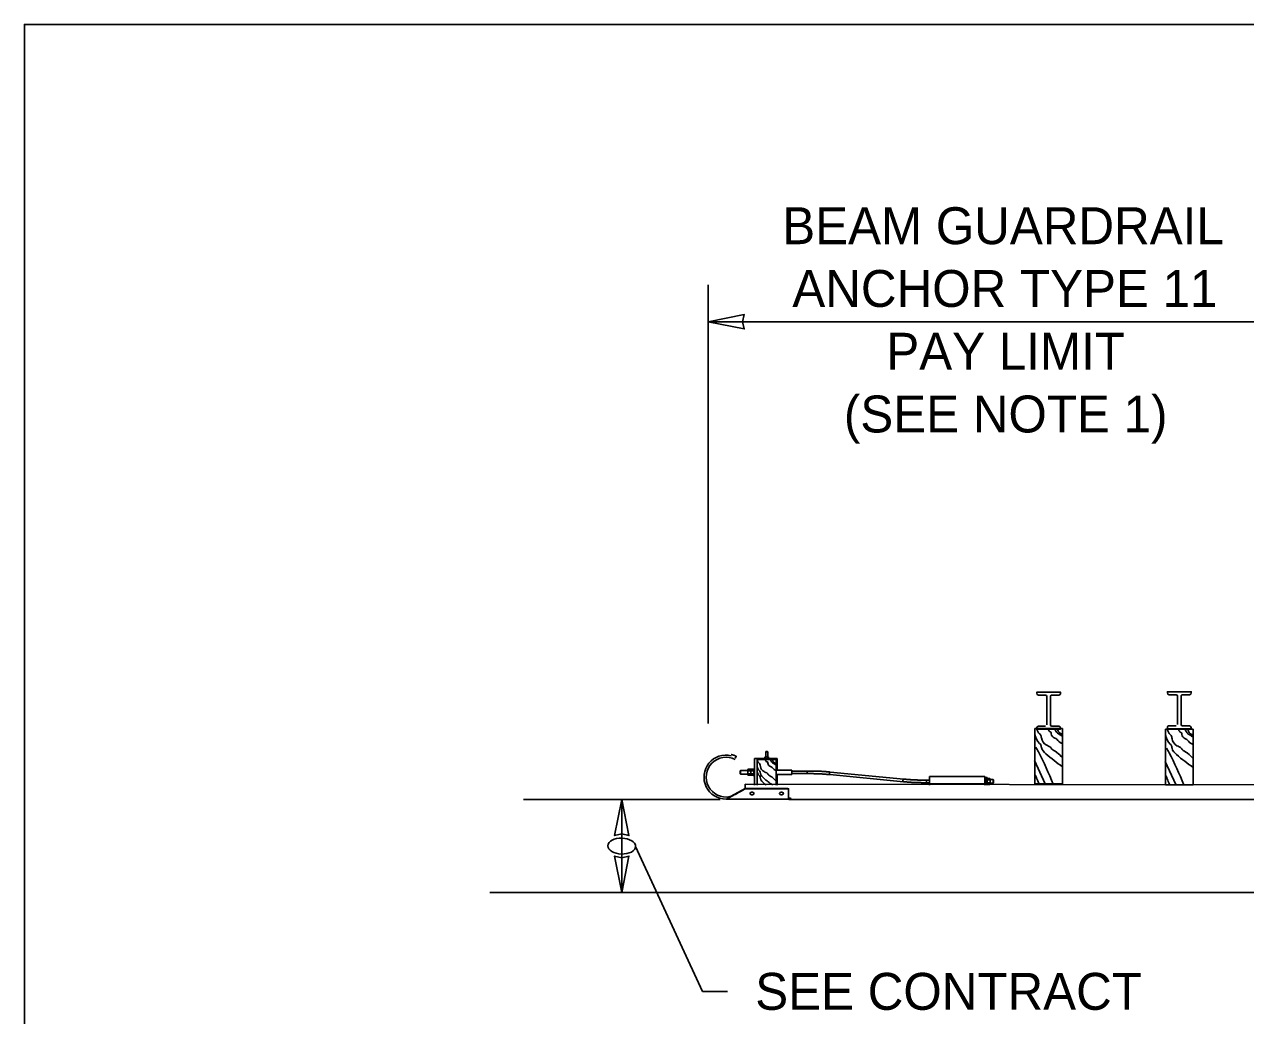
# Model space of a CAD drawing. Extents: x 99862 to 103680, y 99470 to 102076.
# Drawn here: x 99862 to 100391, y 101646 to 102076 of the extents above; entities that cross this region are included whole.
import ezdxf

# ---------------------------------------------------------------- set-up
doc = ezdxf.new("R2010")
doc.units = 0
for name, color, linetype in [('Level 1', 7, 'Continuous'), ('Level 11', 7, 'Continuous'), ('Level 13', 7, 'Continuous'), ('Level 15', 7, 'Continuous'), ('Level 18', 7, 'Continuous'), ('Level 2', 7, 'Continuous'), ('Level 20', 7, 'Continuous'), ('Level 3', 7, 'Continuous'), ('Level 4', 7, 'Continuous'), ('Level 5', 7, 'Continuous'), ('Level 6', 7, 'Continuous'), ('Level 7', 7, 'Continuous'), ('Level 9', 7, 'Continuous')]:
    doc.layers.add(name, color=color, linetype=linetype)

msp = doc.modelspace()

# ---------------------------------------------------------------- linework, layer by layer
at = {"layer": 'Level 1'}
msp.add_lwpolyline([(99862, 99999.5), (103151, 99999.5), (103151, 102075.5), (99862, 102075.5)], close=True, dxfattribs=at)
at = {"layer": 'Level 11'}
msp.add_line((100063.75, 101699.31), (101794.56, 101699.31), dxfattribs=at)
at = {"layer": 'Level 13'}
for p, q in [((100299.86, 101756.4), (100304.44, 101746.38)), ((100356.48, 101756.08), (100361.06, 101746.06))]:
    msp.add_line(p, q, dxfattribs=at)
for points in [[(100299.95, 101768.04), (100302.04, 101763.89), (100302.49, 101763.48), (100302.85, 101762.09), (100304.79, 101759.37), (100311.98, 101753.77)], [(100300.77, 101770.29), (100302.04, 101768.02), (100302.49, 101767.61), (100302.85, 101766.22), (100304.96, 101763.19), (100306.87, 101762.1), (100307.28, 101761.56), (100309.41, 101760.1), (100309.59, 101759.96), (100312.01, 101757.67)], [(100305.74, 101770.29), (100306.56, 101768.93), (100306.95, 101768.76), (100307.12, 101768.05), (100308.36, 101766.28), (100309.6, 101765.62), (100309.92, 101765.18), (100311.98, 101763.77)], [(100308.44, 101770.3), (100308.85, 101769.61), (100309.75, 101768.32), (100310.74, 101767.72), (100311.91, 101766.98)], [(100309.85, 101770.26), (100310.2, 101768.94), (100311.91, 101767.81)], [(100356.57, 101767.73), (100358.66, 101763.58), (100359.11, 101763.17), (100359.46, 101761.78), (100361.4, 101759.06), (100368.6, 101753.46)], [(100357.39, 101769.98), (100358.66, 101767.7), (100359.11, 101767.29), (100359.46, 101765.9), (100361.58, 101762.88), (100363.49, 101761.78), (100363.9, 101761.24), (100366.03, 101759.78), (100366.21, 101759.65), (100368.62, 101757.36)], [(100362.36, 101769.97), (100363.17, 101768.61), (100363.57, 101768.45), (100363.74, 101767.73), (100364.98, 101765.96), (100366.21, 101765.3), (100366.54, 101764.86), (100368.6, 101763.45)], [(100365.06, 101769.98), (100365.47, 101769.29), (100366.37, 101768), (100367.36, 101767.41), (100368.53, 101766.67)], [(100366.47, 101769.95), (100366.82, 101768.63), (100368.53, 101767.5)], [(100300.4, 101762.18), (100301.54, 101760.17), (100307.93, 101746.23)], [(100357.02, 101761.86), (100358.16, 101759.85), (100364.55, 101745.92)], [(100179.71, 101756.66), (100180.43, 101755.25), (100180.77, 101754.95), (100181.04, 101753.9), (100182.63, 101751.64), (100184.07, 101750.82), (100184.37, 101750.41), (100185.97, 101749.32), (100186.11, 101749.22), (100187.92, 101747.51)], [(100183.21, 101756.96), (100183.82, 101755.94), (100184.12, 101755.82), (100184.24, 101755.28), (100185.18, 101753.96), (100186.1, 101753.46), (100186.35, 101753.13), (100187.89, 101752.08)], [(100185.23, 101756.97), (100185.54, 101756.45), (100186.22, 101755.49), (100186.96, 101755.04), (100187.84, 101754.49)], [(100186.29, 101756.95), (100186.55, 101755.96), (100187.84, 101755.11)], [(100179.7, 101753.68), (100180.44, 101752.16), (100180.78, 101751.85), (100181.05, 101750.81), (100182.51, 101748.77), (100186.25, 101745.84)], [(100179.7, 101751.51), (100180.44, 101749.99), (100180.78, 101749.68), (100181.05, 101748.64), (100182.51, 101746.6), (100183.53, 101745.8)], [(100299.96, 101750.47), (100300.11, 101750.21), (100300.25, 101749.95), (100300.52, 101749.41), (100301.01, 101748.29), (100301.46, 101747.16), (100301.69, 101746.6), (100301.93, 101746.04)], [(100356.57, 101750.15), (100356.73, 101749.9), (100356.87, 101749.63), (100357.14, 101749.09), (100357.63, 101747.98), (100358.08, 101746.85), (100358.31, 101746.28), (100358.55, 101745.73)]]:
    msp.add_spline(points, degree=3, dxfattribs=at)
at = {"layer": 'Level 15'}
for p, q in [((100158.32, 101962.65), (100158.32, 101772.53)), ((100419.5, 101946.65), (100158.32, 101946.65)), ((100163.53, 101739.62), (100078.32, 101739.62)), ((100120.92, 101699.31), (100120.92, 101739.62)), ((100126.92, 101719.21), (100155.93, 101656.41)), ((100155.93, 101656.41), (100166.79, 101656.41))]:
    msp.add_line(p, q, dxfattribs=at)
for points in [[(100158.32, 101946.65), (100174.04, 101943.56), (100173.32, 101946.65), (100174.04, 101949.73)], [(100120.92, 101739.62), (100117.84, 101723.9), (100120.92, 101724.63), (100124.01, 101723.9)], [(100120.92, 101699.31), (100117.84, 101715.03), (100120.92, 101714.3), (100124.01, 101715.03)]]:
    msp.add_lwpolyline(points, close=True, dxfattribs=at)
msp.add_ellipse((100120.92, 101719.37), major_axis=(-6, 0.16), ratio=0.57735, dxfattribs=at)
at = {"layer": 'Level 18'}
for p, q in [((100556.25, 101745.69), (100174.41, 101746.25)), ((100419.5, 101739.62), (100193.38, 101739.62))]:
    msp.add_line(p, q, dxfattribs=at)
at = {"layer": 'Level 2'}
for p, q in [((100174.41, 101744.26), (100174.41, 101746.25)), ((100174.41, 101745.81), (100174.41, 101745.84))]:
    msp.add_line(p, q, dxfattribs=at)
at = {"layer": 'Level 3'}
for p, q in [((100170.56, 101758.24), (100170.13, 101757.41)), ((100183.32, 101760.21), (100183.45, 101760.34)), ((100183.32, 101760.21), (100184.26, 101760.21)), ((100183.32, 101758.03), (100183.32, 101760.21)), ((100183.45, 101760.34), (100184.12, 101760.34)), ((100184.12, 101760.34), (100184.26, 101760.21)), ((100184.26, 101760.21), (100184.26, 101758.03)), ((100174.39, 101744.26), (100166.72, 101740.19)), ((100192.77, 101744.26), (100174.39, 101744.26)), ((100192.77, 101744.15), (100174.44, 101744.14)), ((100177.56, 101742.74), (100177.23, 101742.74)), ((100177.56, 101741.64), (100177.23, 101741.64)), ((100190.31, 101742.74), (100189.98, 101742.74)), ((100190.31, 101741.64), (100189.98, 101741.64)), ((100193.14, 101744.35), (100193.14, 101744.46)), ((100193.14, 101740.42), (100193.14, 101743.85)), ((100193.14, 101740.42), (100193.14, 101739.7)), ((100193.14, 101739.7), (100174.39, 101739.7))]:
    msp.add_line(p, q, dxfattribs=at)
for radius, start, end in [(9.56, 76.3846, 270.2805), (8.62, 62.498, 281.2468)]:
    msp.add_arc((100166.14, 101749.26), radius, start, end, dxfattribs=at)
for centre, major_axis, start_param, end_param in [((100177.23, 101742.19), (0.68, 0), 1.570796, 4.712389), ((100177.56, 101742.19), (0.68, 0), 4.712389, 7.853982), ((100189.98, 101742.19), (0.68, 0), 1.570796, 4.712389), ((100190.31, 101742.19), (0.68, 0), 4.712389, 7.853982), ((100192.77, 101743.96), (-0.375, 0), 3.141593, 4.712389), ((100192.77, 101743.85), (-0.375, 0), 3.141593, 4.712389)]:
    msp.add_ellipse(centre, major_axis=major_axis, ratio=0.807578, start_param=start_param, end_param=end_param, dxfattribs=at)
for points, degree in [([(100168.39, 101759.06), (100169.62, 101758.76), (100170.56, 101758.24), (100170.56, 101758.24)], 2), ([(100174.44, 101744.14), (100171.71, 101742.66), (100168.98, 101741.18), (100166.23, 101739.72), (100166.22, 101739.71), (100166.2, 101739.71), (100166.19, 101739.7)], 3), ([(100193.52, 101739.99), (100193.49, 101739.97), (100193.43, 101739.94), (100193.34, 101739.91), (100193.25, 101739.89), (100193.18, 101739.89), (100193.14, 101739.89)], 3), ([(100193.97, 101740.24), (100193.68, 101740.08), (100193.52, 101739.99)], 2), ([(100194.34, 101740.24), (100194.19, 101740.16), (100194.06, 101740.08), (100193.77, 101739.92), (100193.61, 101739.82)], 3), ([(100174.39, 101739.7), (100171.64, 101739.7), (100168.89, 101739.7), (100166.14, 101739.7)], 2), ([(100166.19, 101739.7), (100166.19, 101739.7), (100166.19, 101739.7), (100166.19, 101739.7)], 2), ([(100193.61, 101739.82), (100193.46, 101739.74), (100193.34, 101739.7), (100193.14, 101739.7)], 2), ([(100193.14, 101739.7), (100193.14, 101739.7), (100193.14, 101739.7), (100193.14, 101739.7)], 2)]:
    msp.add_open_spline(points, degree=degree, dxfattribs=at)
at = {"layer": 'Level 4'}
for p, q in [((100299.97, 101770.29), (100311.97, 101770.29)), ((100299.97, 101770.29), (100299.97, 101746.29)), ((100311.97, 101746.29), (100311.97, 101770.29)), ((100356.59, 101769.98), (100368.59, 101769.98)), ((100356.59, 101769.98), (100356.59, 101745.98)), ((100368.59, 101745.98), (100368.59, 101769.98)), ((100182.98, 101757.34), (100179.66, 101757.34)), ((100181.54, 101757.06), (100179.66, 101757.06)), ((100187.91, 101756.96), (100179.66, 101756.96)), ((100179.66, 101756.96), (100179.66, 101745.84)), ((100188.29, 101757.34), (100184.6, 101757.34)), ((100188.01, 101757.06), (100186.04, 101757.06)), ((100187.91, 101745.84), (100187.91, 101756.96)), ((100188.01, 101752.28), (100188.01, 101757.06)), ((100188.29, 101752.28), (100188.29, 101757.34)), ((100188.01, 101745.84), (100188.01, 101750.4)), ((100188.29, 101745.84), (100188.29, 101750.4)), ((100299.97, 101746.29), (100311.97, 101746.29)), ((100356.59, 101745.98), (100368.59, 101745.98))]:
    msp.add_line(p, q, dxfattribs=at)
at = {"layer": 'Level 5'}
for p, q in [((100186.04, 101757.21), (100181.54, 101757.21)), ((100181.54, 101757.21), (100181.54, 101756.96)), ((100186.04, 101757.21), (100186.04, 101756.96))]:
    msp.add_line(p, q, dxfattribs=at)
at = {"layer": 'Level 6'}
for p, q in [((100172.29, 101751.96), (100172.42, 101752.09)), ((100172.29, 101750.72), (100172.29, 101751.96)), ((100172.29, 101751.96), (100172.29, 101751.96)), ((100172.42, 101750.59), (100172.29, 101750.72)), ((100172.42, 101750.59), (100172.42, 101752.09)), ((100172.42, 101752.09), (100175.57, 101752.09)), ((100175.57, 101750.59), (100172.42, 101750.59)), ((100187.91, 101752.28), (100194.69, 101752.28)), ((100194.69, 101750.4), (100194.69, 101752.28)), ((100194.69, 101752.28), (100194.69, 101752.28)), ((100194.69, 101751.9), (100201.24, 101751.9)), ((100201.24, 101750.78), (100194.69, 101750.78)), ((100201.24, 101751.9), (100201.24, 101750.78)), ((100211.28, 101751.46), (100243.15, 101748.41)), ((100194.69, 101750.4), (100187.91, 101750.4)), ((100243.04, 101747.29), (100211.17, 101750.34)), ((100253.08, 101747.98), (100253.08, 101746.85)), ((100253.08, 101747.98), (100254.29, 101747.98)), ((100254.29, 101746.85), (100253.08, 101746.85)), ((100254.29, 101749.55), (100278.29, 101749.55)), ((100254.29, 101749.55), (100254.29, 101746.32)), ((100254.29, 101746.32), (100278.29, 101746.32)), ((100254.29, 101746.32), (100254.29, 101745.84)), ((100278.29, 101749.55), (100278.29, 101745.84)), ((100278.29, 101749.1), (100279.04, 101749.1)), ((100279.04, 101749.1), (100279.04, 101745.84)), ((100280.6, 101748.17), (100281.9, 101748.17)), ((100281.9, 101746.67), (100280.6, 101746.67)), ((100281.9, 101748.17), (100281.9, 101746.67)), ((100281.9, 101748.17), (100282.04, 101748.03)), ((100282.04, 101746.8), (100281.9, 101746.67)), ((100282.04, 101748.03), (100282.04, 101746.8)), ((100282.04, 101746.8), (100282.04, 101746.8))]:
    msp.add_line(p, q, dxfattribs=at)
for centre, start_param in [((100211.23, 101750.9), 3.141597), ((100243.1, 101747.85), 3.141588)]:
    msp.add_ellipse(centre, major_axis=(-0.054, -0.56), ratio=0.548823, start_param=start_param, end_param=6.283185, dxfattribs=at)
for points in [[(100201.24, 101751.9), (100204.79, 101751.9), (100208.33, 101751.75), (100211.28, 101751.46)], [(100211.17, 101750.34), (100208.26, 101750.62), (100204.75, 101750.78), (100201.24, 101750.78)], [(100253.08, 101746.85), (100249.54, 101746.85), (100246, 101747.01), (100243.04, 101747.29)], [(100243.15, 101748.41), (100246.06, 101748.13), (100249.57, 101747.98), (100253.08, 101747.98)]]:
    msp.add_open_spline(points, degree=2, dxfattribs=at)
at = {"layer": 'Level 7'}
for p, q in [((100178.44, 101757.34), (100178.44, 101745.84)), ((100178.44, 101757.34), (100179.66, 101757.34)), ((100179.66, 101757.34), (100179.66, 101756.96))]:
    msp.add_line(p, q, dxfattribs=at)
at = {"layer": 'Level 9'}
for p, q in [((100305.23, 101784.19), (100305.22, 101778.06)), ((100306.76, 101778.05), (100306.77, 101784.19)), ((100361.84, 101784.38), (100361.84, 101778.24)), ((100363.38, 101778.24), (100363.39, 101784.38)), ((100305.22, 101778.06), (100305.21, 101771.92)), ((100306.75, 101771.92), (100306.76, 101778.05)), ((100361.84, 101778.24), (100361.83, 101772.11)), ((100363.37, 101772.1), (100363.38, 101778.24)), ((100182.97, 101757.97), (100183.08, 101758.03)), ((100182.98, 101757.97), (100182.98, 101757.21)), ((100183.79, 101758.03), (100183.08, 101758.03)), ((100183.38, 101757.97), (100183.38, 101757.21)), ((100184.39, 101758.03), (100183.79, 101758.03)), ((100184.19, 101757.97), (100184.19, 101757.21)), ((100184.26, 101758.55), (100184.26, 101758.55)), ((100184.26, 101758.55), (100184.26, 101758.55)), ((100184.39, 101758.03), (100184.4, 101758.03)), ((100184.49, 101758.03), (100184.4, 101758.03)), ((100184.49, 101758.03), (100184.6, 101757.97)), ((100184.6, 101757.97), (100184.6, 101757.21)), ((100187.91, 101756.31), (100188.01, 101756.31)), ((100175.57, 101752.46), (100175.67, 101752.64)), ((100175.57, 101752.46), (100175.57, 101752.32)), ((100175.57, 101752.3), (100175.57, 101752.32)), ((100175.57, 101752.3), (100175.57, 101751.34)), ((100175.57, 101751.34), (100175.57, 101750.21)), ((100175.67, 101752.64), (100176.88, 101752.64)), ((100175.67, 101751.99), (100176.88, 101751.99)), ((100175.67, 101750.69), (100176.88, 101750.69)), ((100176.88, 101752.46), (100176.98, 101752.64)), ((100176.88, 101751.99), (100176.88, 101752.64)), ((100176.88, 101752.3), (100176.88, 101752.32)), ((100176.88, 101750.69), (100176.88, 101751.99)), ((100176.88, 101751.34), (100176.88, 101751.34)), ((100176.88, 101751.34), (100176.88, 101751.34)), ((100176.88, 101750.04), (100176.88, 101750.69)), ((100176.98, 101752.64), (100178.19, 101752.64)), ((100176.98, 101751.99), (100178.19, 101751.99)), ((100176.98, 101750.69), (100178.19, 101750.69)), ((100178.19, 101753.01), (100178.44, 101753.01)), ((100178.19, 101749.67), (100178.19, 101753.01)), ((100178.19, 101752.64), (100178.19, 101753.01)), ((100178.19, 101751.99), (100178.19, 101752.64)), ((100178.19, 101750.69), (100178.19, 101751.99)), ((100178.19, 101750.04), (100178.19, 101750.69)), ((100188.01, 101755.37), (100187.91, 101755.37)), ((100175.67, 101750.04), (100175.57, 101750.21)), ((100175.67, 101750.04), (100176.88, 101750.04)), ((100176.98, 101750.04), (100176.88, 101750.21)), ((100176.98, 101750.04), (100178.19, 101750.04)), ((100178.19, 101749.67), (100178.44, 101749.67)), ((100279.29, 101749.08), (100279.04, 101749.08)), ((100279.29, 101749.08), (100279.29, 101745.84)), ((100280.5, 101748.72), (100279.29, 101748.72)), ((100279.29, 101748.72), (100279.29, 101748.07)), ((100280.5, 101748.07), (100279.29, 101748.07)), ((100279.29, 101748.07), (100279.29, 101746.77)), ((100279.29, 101746.77), (100279.29, 101746.12)), ((100280.5, 101746.77), (100279.29, 101746.77)), ((100279.29, 101746.12), (100279.29, 101745.84)), ((100280.5, 101746.12), (100279.29, 101746.12)), ((100280.5, 101748.72), (100280.6, 101748.54)), ((100280.6, 101746.29), (100280.5, 101746.12)), ((100280.6, 101747.42), (100280.6, 101748.54)), ((100280.6, 101746.45), (100280.6, 101747.42)), ((100280.6, 101746.45), (100280.6, 101746.43)), ((100280.6, 101746.29), (100280.6, 101746.43))]:
    msp.add_line(p, q, dxfattribs=at)
for points in [[(100306, 101786.05), (100300.83, 101786.06), (100300.83, 101785.58)], [(100301.62, 101784.79), (100304.64, 101784.78)], [(100311.17, 101785.56), (100311.17, 101786.05), (100306, 101786.05)], [(100307.36, 101784.78), (100310.38, 101784.78)], [(100362.62, 101786.24), (100357.45, 101786.25), (100357.45, 101785.76)], [(100358.23, 101784.98), (100361.25, 101784.97)], [(100367.79, 101785.75), (100367.79, 101786.24), (100362.62, 101786.24)], [(100363.98, 101784.97), (100367, 101784.96)], [(100300.81, 101770.54), (100300.81, 101770.06), (100305.98, 101770.05)], [(100304.62, 101771.33), (100301.6, 101771.33)], [(100305.98, 101770.05), (100311.15, 101770.05), (100311.15, 101770.53)], [(100310.36, 101771.32), (100307.34, 101771.32)], [(100357.43, 101770.73), (100357.43, 101770.25), (100362.6, 101770.24)], [(100361.24, 101771.52), (100358.22, 101771.52)], [(100362.6, 101770.24), (100367.77, 101770.24), (100367.77, 101770.72)], [(100366.98, 101771.51), (100363.96, 101771.51)]]:
    msp.add_lwpolyline(points, dxfattribs=at)
for centre, radius, start, end in [((100301.62, 101785.58), 0.788, 179.9273, 269.9273), ((100304.63, 101784.19), 0.591, 359.9273, 89.9273), ((100307.36, 101784.19), 0.591, 89.9273, 179.9273), ((100310.38, 101785.56), 0.788, 269.9273, 359.9273), ((100358.23, 101785.76), 0.788, 179.9273, 269.9273), ((100361.25, 101784.38), 0.591, 359.9273, 89.9273), ((100363.98, 101784.38), 0.591, 89.9273, 179.9273), ((100367, 101785.75), 0.788, 269.9273, 359.9273), ((100307.34, 101771.92), 0.591, 179.9273, 269.9273), ((100363.96, 101772.1), 0.591, 179.9273, 269.9273), ((100301.6, 101770.54), 0.788, 89.9273, 179.9478), ((100310.36, 101770.53), 0.788, 359.9478, 89.9273), ((100358.22, 101770.73), 0.788, 89.9273, 179.9478), ((100366.98, 101770.72), 0.788, 359.9478, 89.9273)]:
    msp.add_arc(centre, radius, start, end, dxfattribs=at)
for points, degree in [([(100182.98, 101757.97), (100183.04, 101758.01), (100183.11, 101758.03), (100183.25, 101758.03), (100183.31, 101758.01), (100183.38, 101757.97)], 3), ([(100182.98, 101757.97), (100182.98, 101757.97), (100182.98, 101757.97), (100182.98, 101757.97)], 2), ([(100183.79, 101758.03), (100183.65, 101758.03), (100183.51, 101758.01), (100183.38, 101757.97)], 2), ([(100184.19, 101757.97), (100184.06, 101758.01), (100183.92, 101758.03), (100183.79, 101758.03)], 2), ([(100184.19, 101757.97), (100184.26, 101758.01), (100184.32, 101758.03), (100184.39, 101758.03)], 2), ([(100184.4, 101758.03), (100184.47, 101758.03), (100184.53, 101758.01), (100184.6, 101757.97)], 2), ([(100184.6, 101757.97), (100184.6, 101757.97), (100184.6, 101757.97), (100184.6, 101757.97)], 2), ([(100175.57, 101752.32), (100175.57, 101752.43), (100175.61, 101752.54), (100175.67, 101752.64)], 2), ([(100175.67, 101751.99), (100175.61, 101752.09), (100175.57, 101752.19), (100175.57, 101752.3)], 2), ([(100175.67, 101751.99), (100175.61, 101751.78), (100175.57, 101751.56), (100175.57, 101751.34)], 2), ([(100175.57, 101751.34), (100175.57, 101751.12), (100175.61, 101750.9), (100175.67, 101750.69)], 2), ([(100175.67, 101750.04), (100175.61, 101750.15), (100175.57, 101750.25), (100175.57, 101750.47), (100175.61, 101750.58), (100175.67, 101750.69)], 3), ([(100176.88, 101752.32), (100176.88, 101752.43), (100176.92, 101752.54), (100176.98, 101752.64)], 2), ([(100176.98, 101751.99), (100176.92, 101752.09), (100176.88, 101752.19), (100176.88, 101752.3)], 2), ([(100176.98, 101751.99), (100176.92, 101751.78), (100176.88, 101751.56), (100176.88, 101751.34)], 2), ([(100176.88, 101751.34), (100176.88, 101751.12), (100176.92, 101750.9), (100176.98, 101750.69)], 2), ([(100176.98, 101750.04), (100176.92, 101750.15), (100176.88, 101750.25), (100176.88, 101750.47), (100176.92, 101750.58), (100176.98, 101750.69)], 3), ([(100175.67, 101750.04), (100175.67, 101750.04), (100175.67, 101750.04), (100175.67, 101750.04)], 2), ([(100176.98, 101750.04), (100176.98, 101750.04), (100176.98, 101750.04), (100176.98, 101750.04)], 2), ([(100280.5, 101748.72), (100280.5, 101748.72), (100280.5, 101748.72), (100280.5, 101748.72)], 2), ([(100280.5, 101748.72), (100280.56, 101748.61), (100280.6, 101748.5), (100280.6, 101748.28), (100280.56, 101748.17), (100280.5, 101748.07)], 3), ([(100280.6, 101747.42), (100280.6, 101747.64), (100280.56, 101747.86), (100280.5, 101748.07)], 2), ([(100280.5, 101746.77), (100280.56, 101746.98), (100280.6, 101747.2), (100280.6, 101747.42)], 2), ([(100280.5, 101746.77), (100280.56, 101746.67), (100280.6, 101746.56), (100280.6, 101746.45)], 2), ([(100280.6, 101746.43), (100280.6, 101746.32), (100280.56, 101746.22), (100280.5, 101746.12)], 2), ([(100280.5, 101746.12), (100280.5, 101746.12), (100280.5, 101746.12), (100280.5, 101746.12)], 2)]:
    msp.add_open_spline(points, degree=degree, dxfattribs=at)

# ---------------------------------------------------------------- texts
at = {"layer": 'Level 20'}
for s, p in [('BEAM GUARDRAIL', (100190.5, 101980.25)), ('ANCHOR TYPE 11', (100194.88, 101953.05)), ('PAY LIMIT', (100235.62, 101925.85)), ('(SEE NOTE 1)', (100217.22, 101898.65)), ('SEE CONTRACT', (100178.79, 101648.41))]:
    msp.add_text(s, height=16, dxfattribs=at).set_placement(p)

doc.saveas('drawing.dxf')
